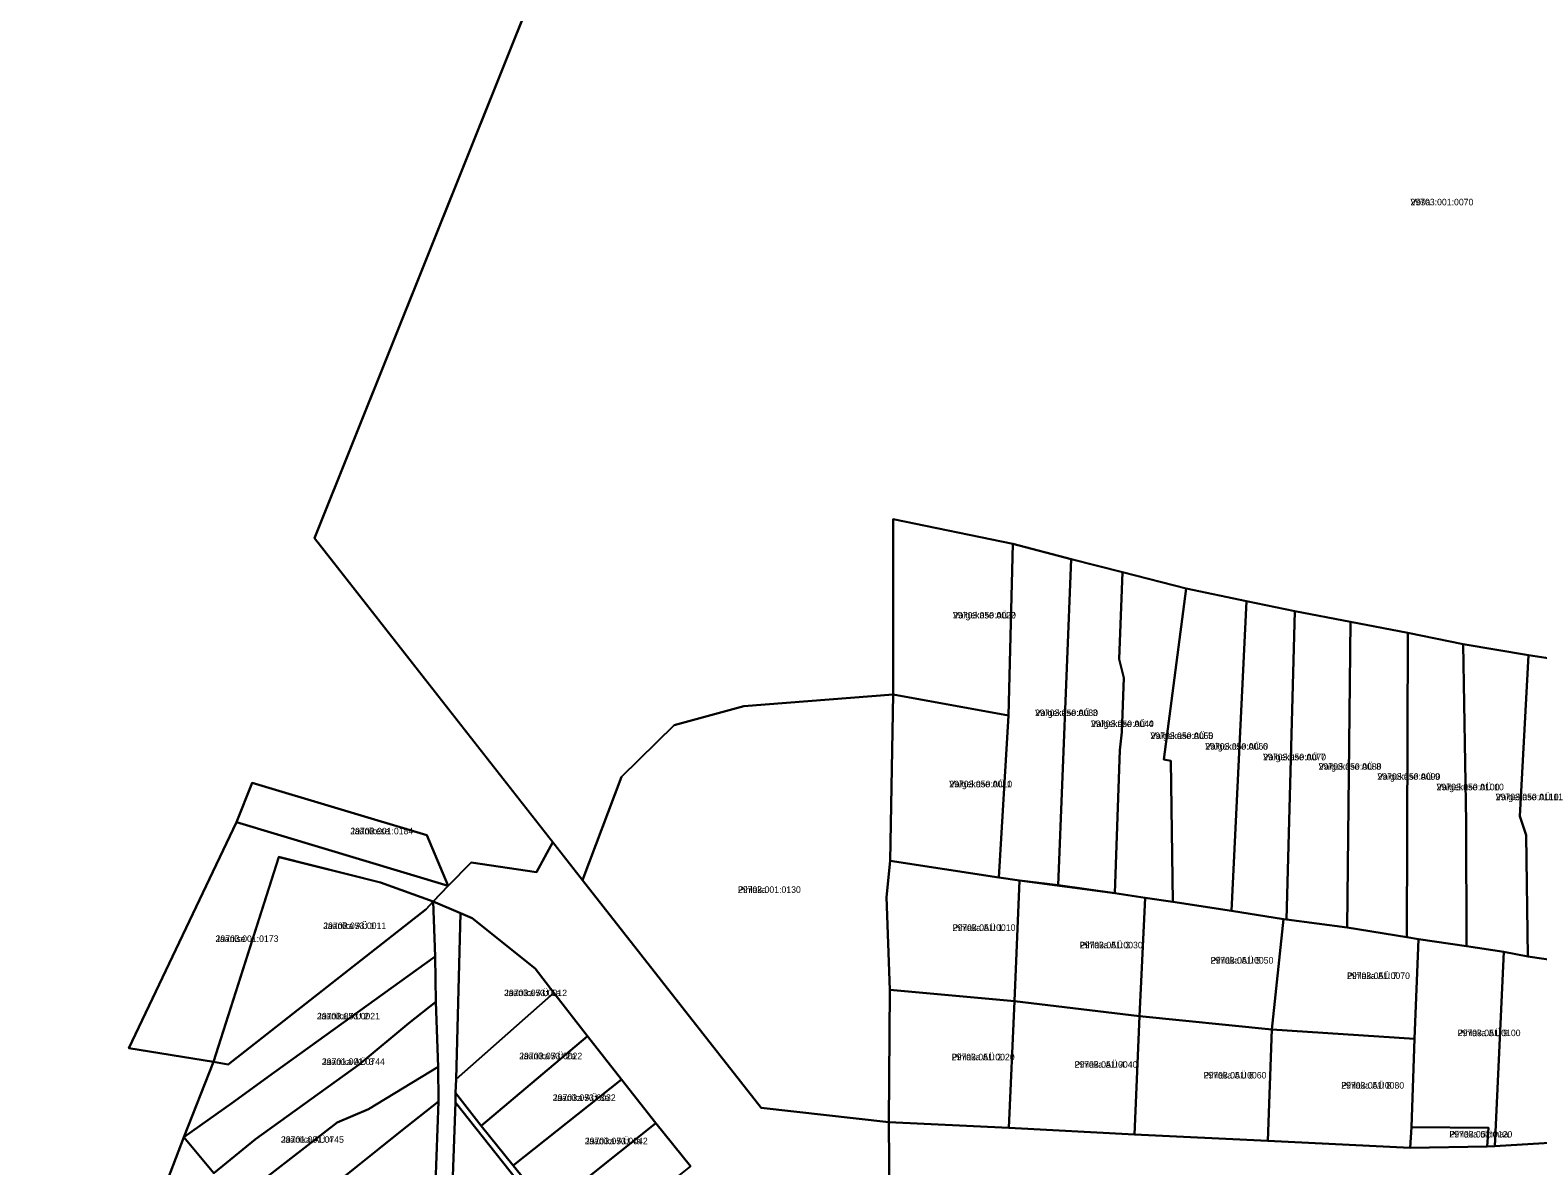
# Model space of a CAD drawing. Extents: x 504287 to 537970, y 6539941 to 6586214.
# Drawn here: x 519918.3 to 520265.8, y 6560574.3 to 6560836.1 of the extents above; entities that cross this region are included whole.
import ezdxf

# ---------------------------------------------------------------- set-up
doc = ezdxf.new("R2010")
doc.units = 0
for name, color, linetype in [('L_AADRESS', 7, 'Continuous'), ('PIIR', 7, 'Continuous'), ('TUNNUS', 7, 'Continuous')]:
    doc.layers.add(name, color=color, linetype=linetype)

msp = doc.modelspace()

# ---------------------------------------------------------------- linework, layer by layer
at = {"layer": 'PIIR'}
for points in [[(520271.61, 6560690.76), (520263.59, 6560691.99), (520248.53, 6560694.54), (520235.8, 6560697.16), (520222.62, 6560699.66), (520209.74, 6560702.15), (520198.62, 6560704.47), (520184.75, 6560707.39), (520170.04, 6560711.12), (520158.24, 6560714.13), (520144.79, 6560717.67), (520117.24, 6560723.36), (520117.22, 6560682.92), (520082.78, 6560680.28), (520066.74, 6560675.85), (520054.61, 6560663.99), (520045.66, 6560640.15), (519983.84, 6560719), (520056.26, 6560899.71)], [(520034.88, 6560846.36), (519983.84, 6560719), (520038.76, 6560648.94), (520035.01, 6560641.99), (520019.98, 6560644.23), (520014.71, 6560638.85), (520009.74, 6560650.5), (519969.54, 6560662.58), (519965.91, 6560653.52), (519941.08, 6560601.39), (519960.59, 6560598.29), (519953.78, 6560580.87), (519946.8, 6560562.5), (519943.46, 6560547.11), (519940.24, 6560531.14), (519938, 6560520.67), (519932.24, 6560494.3), (519926.01, 6560463.67), (519884.76, 6560514.86)], [(520070.55, 6560574.23), (520062.55, 6560584.16), (520054.64, 6560594.18), (520046.76, 6560604.18), (520039.04, 6560614.2), (520034.75, 6560619.78), (520020.24, 6560631.37), (520017.51, 6560632.51), (520011.19, 6560635.24), (520014.71, 6560638.85), (520019.98, 6560644.23), (520035.01, 6560641.99), (520038.76, 6560648.94), (520045.66, 6560640.15), (520086.83, 6560587.63), (520116.2, 6560584.35), (520116.35, 6560565.44)], [(520011.74, 6560570.25), (520012.48, 6560589.11), (520012.38, 6560597.12), (520011.86, 6560612.09), (520011.71, 6560622.51), (520011.19, 6560635.24), (520017.51, 6560632.51), (520016.5, 6560594.3), (520016.36, 6560591.12), (520016.33, 6560588.87), (520014.83, 6560546.37)], [(520036.54, 6560563.34), (520016.33, 6560588.87), (520016.36, 6560591.12), (520022.31, 6560583.51), (520029.67, 6560574.33), (520037.78, 6560564.36)]]:
    msp.add_lwpolyline(points, dxfattribs=at)
for points in [[(520117.24, 6560723.36), (520144.79, 6560717.67), (520143.77, 6560678.14), (520117.22, 6560682.92)], [(520141.59, 6560640.75), (520143.77, 6560678.14), (520144.79, 6560717.67), (520158.24, 6560714.13), (520155.24, 6560638.97), (520146.3, 6560640.09)], [(520158.24, 6560714.13), (520170.04, 6560711.12), (520169.29, 6560691.08), (520170.34, 6560686.77), (520169.91, 6560674.24), (520169.47, 6560670.14), (520168.26, 6560637.17), (520155.24, 6560638.97)], [(520168.26, 6560637.17), (520169.47, 6560670.14), (520169.91, 6560674.24), (520170.34, 6560686.77), (520169.29, 6560691.08), (520170.04, 6560711.12), (520184.75, 6560707.39), (520179.62, 6560667.98), (520181.17, 6560667.66), (520181.69, 6560635.15), (520175.32, 6560636.07)], [(520181.17, 6560667.66), (520179.62, 6560667.98), (520184.75, 6560707.39), (520198.62, 6560704.47), (520195.17, 6560633.08), (520181.69, 6560635.15)], [(520198.62, 6560704.47), (520209.74, 6560702.15), (520207.89, 6560631.08), (520207.16, 6560631.13), (520195.17, 6560633.08)], [(520209.74, 6560702.15), (520222.62, 6560699.66), (520221.81, 6560629.26), (520207.89, 6560631.08)], [(520222.62, 6560699.66), (520235.8, 6560697.16), (520235.55, 6560626.97), (520221.81, 6560629.26)], [(520235.55, 6560626.97), (520235.8, 6560697.16), (520248.53, 6560694.54), (520249.27, 6560653.5), (520249.33, 6560624.96), (520238.26, 6560626.53)], [(520249.27, 6560653.5), (520248.53, 6560694.54), (520263.59, 6560691.99), (520261.64, 6560654.9), (520263.11, 6560650.54), (520263.46, 6560622.57), (520257.91, 6560623.6), (520249.33, 6560624.96)], [(520263.11, 6560650.54), (520261.64, 6560654.9), (520263.59, 6560691.99), (520271.61, 6560690.76), (520272.14, 6560691.85), (520276.25, 6560690.73), (520276.73, 6560687), (520275.62, 6560683.17), (520276.47, 6560664.61), (520277.3, 6560651.87), (520279.05, 6560620.33), (520276.64, 6560620.62), (520263.46, 6560622.57)], [(520116.51, 6560644.62), (520115.69, 6560636.23), (520116.43, 6560614.85), (520116.2, 6560584.35), (520086.83, 6560587.63), (520045.66, 6560640.15), (520054.61, 6560663.99), (520066.74, 6560675.85), (520082.78, 6560680.28), (520117.22, 6560682.92)], [(520117.22, 6560682.92), (520143.77, 6560678.14), (520141.59, 6560640.75), (520116.51, 6560644.62)], [(519969.54, 6560662.58), (520009.74, 6560650.5), (520014.71, 6560638.85), (519965.91, 6560653.52)], [(519965.91, 6560653.52), (520014.71, 6560638.85), (520011.19, 6560635.24), (519999.07, 6560639.62), (519975.64, 6560645.52), (519960.59, 6560598.29), (519941.08, 6560601.39)], [(519999.06, 6560639.6), (520011.19, 6560635.24), (520009.57, 6560633.48), (519964.01, 6560597.62), (519960.62, 6560598.26), (519975.66, 6560645.47)], [(520115.69, 6560636.23), (520116.51, 6560644.62), (520141.59, 6560640.75), (520146.3, 6560640.09), (520145.21, 6560612.28), (520116.43, 6560614.85)], [(520146.3, 6560640.09), (520168.26, 6560637.17), (520175.32, 6560636.07), (520174.01, 6560608.77), (520145.21, 6560612.28)], [(519960.62, 6560598.26), (519964.01, 6560597.62), (520009.57, 6560633.48), (520011.19, 6560635.24), (520011.71, 6560622.51), (519974.69, 6560595.86), (519964.83, 6560588.72), (519953.78, 6560580.87)], [(520175.32, 6560636.07), (520181.69, 6560635.15), (520195.17, 6560633.08), (520207.16, 6560631.13), (520204.49, 6560605.75), (520174.01, 6560608.77)], [(520020.24, 6560631.37), (520034.75, 6560619.78), (520039.04, 6560614.2), (520016.5, 6560594.3), (520017.51, 6560632.51)], [(520207.16, 6560631.13), (520207.89, 6560631.08), (520221.81, 6560629.26), (520235.55, 6560626.97), (520238.26, 6560626.53), (520237.32, 6560603.59), (520204.49, 6560605.75)], [(520237.32, 6560603.59), (520238.26, 6560626.53), (520249.33, 6560624.96), (520257.91, 6560623.6), (520255.84, 6560578.81), (520254.12, 6560578.76), (520254.41, 6560583.04), (520236.68, 6560583.22)], [(519960.65, 6560572.6), (519953.78, 6560580.87), (519964.83, 6560588.72), (519974.69, 6560595.86), (520011.71, 6560622.51), (520011.86, 6560612.09), (520005.63, 6560607.16), (519994.2, 6560597.62), (519970.25, 6560580.41)], [(520257.91, 6560623.6), (520263.46, 6560622.57), (520276.64, 6560620.62), (520274.81, 6560579.95), (520255.84, 6560578.81)], [(519946.8, 6560562.5), (519953.78, 6560580.87), (519960.65, 6560572.6), (519970.25, 6560580.41), (519994.2, 6560597.62), (520005.63, 6560607.16), (520011.86, 6560612.09), (520012.38, 6560597.12), (519996.34, 6560587.33), (519989.12, 6560584.31), (519964.15, 6560564.92), (519966.45, 6560560.06), (519956.05, 6560554.39), (519954.98, 6560556.08), (519943.46, 6560547.11)], [(520016.36, 6560591.12), (520016.5, 6560594.3), (520039.04, 6560614.2), (520046.76, 6560604.18), (520022.31, 6560583.51)], [(520116.43, 6560614.85), (520145.21, 6560612.28), (520143.89, 6560583.03), (520116.2, 6560584.35)], [(520145.21, 6560612.28), (520174.01, 6560608.77), (520172.86, 6560581.52), (520143.89, 6560583.03)], [(520174.01, 6560608.77), (520204.49, 6560605.75), (520203.54, 6560580.07), (520172.86, 6560581.52)], [(520204.49, 6560605.75), (520237.32, 6560603.59), (520236.68, 6560583.22), (520236.32, 6560578.42), (520203.54, 6560580.07)], [(520022.31, 6560583.51), (520046.76, 6560604.18), (520054.64, 6560594.18), (520029.67, 6560574.33)], [(519940.24, 6560531.14), (519943.46, 6560547.11), (519954.98, 6560556.08), (519956.05, 6560554.39), (519966.45, 6560560.06), (519964.15, 6560564.92), (519989.12, 6560584.31), (519996.34, 6560587.33), (520012.38, 6560597.12), (520012.48, 6560589.11), (520003.68, 6560582.19), (519998.59, 6560578.1), (519993.62, 6560574.1), (519966.07, 6560551.93)], [(520029.67, 6560574.33), (520054.64, 6560594.18), (520062.55, 6560584.16), (520037.78, 6560564.36)], [(519966.08, 6560551.94), (519993.62, 6560574.1), (519998.59, 6560578.1), (520003.68, 6560582.19), (520012.48, 6560589.11), (520011.74, 6560570.25), (519972.17, 6560543.68)], [(520036.54, 6560563.34), (520014.83, 6560546.37), (520016.33, 6560588.87)], [(520037.78, 6560564.36), (520062.55, 6560584.16), (520070.55, 6560574.23), (520045.75, 6560554.35)], [(520116.2, 6560584.35), (520143.89, 6560583.03), (520172.86, 6560581.52), (520203.54, 6560580.07), (520236.32, 6560578.42), (520254.12, 6560578.76), (520255.84, 6560578.81), (520274.81, 6560579.95), (520296.22, 6560581), (520324.82, 6560582.86), (520329.36, 6560563.63), (520310.39, 6560562.71), (520295.35, 6560561.83), (520280.17, 6560560.87), (520265.21, 6560560.11), (520249.8, 6560559.14), (520244.74, 6560558.9), (520234.71, 6560559.27), (520219.94, 6560560.24), (520173.38, 6560562.51), (520162.65, 6560563.03), (520116.35, 6560565.44)], [(520236.68, 6560583.22), (520254.41, 6560583.04), (520254.12, 6560578.76), (520236.32, 6560578.42)]]:
    msp.add_lwpolyline(points, close=True, dxfattribs=at)

# ---------------------------------------------------------------- texts
at = {"layer": 'L_AADRESS'}
for s, p in [('Võsa', (520236.42, 6560795.72)), ('Valgekase AÜ 2', (520131, 6560700.48)), ('Valgekase AÜ 3', (520149.92, 6560677.98)), ('Valgekase AÜ 4', (520162.79, 6560675.45)), ('Valgekase AÜ 5', (520176.5, 6560672.69)), ('Valgekase AÜ 6', (520189.12, 6560670.24)), ('Valgekase AÜ 7', (520202.46, 6560667.78)), ('Valgekase AÜ 8', (520215.25, 6560665.6)), ('Valgekase AÜ 9', (520228.8, 6560663.29)), ('Valgekase AÜ 1', (520130.14, 6560661.56)), ('Valgekase AÜ 10', (520242.44, 6560660.87)), ('Valgekase AÜ 11', (520256.06, 6560658.58)), ('Jaanikese', (519992.13, 6560650.71)), ('Pihlaka', (520081.44, 6560637.21)), ('Jaanika AÜ 1', (519985.9, 6560628.88)), ('Pihlaka AÜ 1', (520130.9, 6560628.45)), ('Jaanise', (519961.07, 6560625.9)), ('Pihlaka AÜ 3', (520160.22, 6560624.43)), ('Pihlaka AÜ 5', (520190.34, 6560620.91)), ('Pihlaka AÜ 7', (520221.8, 6560617.36)), ('Jaanika AÜ 1a', (520027.57, 6560613.41)), ('Jaanika AÜ 2', (519984.45, 6560608.05)), ('Pihlaka AÜ 9', (520247.29, 6560604.18)), ('Jaanika AÜ 3', (519985.58, 6560597.56)), ('Jaanika AÜ 2a', (520031.06, 6560598.86)), ('Pihlaka AÜ 2', (520130.71, 6560598.62)), ('Pihlaka AÜ 4', (520159.01, 6560596.9)), ('Pihlaka AÜ 6', (520188.74, 6560594.42)), ('Jaanika AÜ 3a', (520038.78, 6560589.25)), ('Pihlaka AÜ 8', (520220.47, 6560592.09)), ('Jaanika AÜ 4', (519976.15, 6560579.6)), ('Jaanika AÜ 4a', (520046.16, 6560579.27)), ('Pihlaka üldmaa', (520245.38, 6560580.82))]:
    msp.add_text(s, height=1.5, dxfattribs=at).set_placement(p)
at = {"layer": 'TUNNUS'}
for s, p in [('29703:001:0070', (520236.42, 6560795.72)), ('29703:050:0020', (520131, 6560700.48)), ('29703:050:0030', (520149.92, 6560677.98)), ('29703:050:0040', (520162.79, 6560675.45)), ('29703:050:0050', (520176.5, 6560672.69)), ('29703:050:0060', (520189.12, 6560670.24)), ('29703:050:0070', (520202.46, 6560667.78)), ('29703:050:0080', (520215.25, 6560665.6)), ('29703:050:0090', (520228.8, 6560663.29)), ('29703:050:0010', (520130.14, 6560661.56)), ('29703:050:0100', (520242.44, 6560660.87)), ('29703:050:0110', (520256.06, 6560658.58)), ('29703:001:0184', (519992.13, 6560650.71)), ('29703:001:0130', (520081.44, 6560637.21)), ('29703:053:0011', (519985.9, 6560628.88)), ('29703:051:0010', (520130.9, 6560628.45)), ('29703:001:0173', (519961.07, 6560625.9)), ('29703:051:0030', (520160.22, 6560624.43)), ('29703:051:0050', (520190.34, 6560620.91)), ('29703:051:0070', (520221.8, 6560617.36)), ('29703:053:0012', (520027.57, 6560613.41)), ('29703:053:0021', (519984.45, 6560608.05)), ('29703:051:0100', (520247.29, 6560604.18)), ('29701:001:0744', (519985.58, 6560597.56)), ('29703:053:0022', (520031.06, 6560598.86)), ('29703:051:0020', (520130.71, 6560598.62)), ('29703:051:0040', (520159.01, 6560596.9)), ('29703:051:0060', (520188.74, 6560594.42)), ('29703:051:0080', (520220.47, 6560592.09)), ('29703:053:0032', (520038.78, 6560589.25)), ('29701:001:0745', (519976.15, 6560579.6)), ('29703:053:0042', (520046.16, 6560579.27)), ('29703:051:0120', (520245.38, 6560580.82))]:
    msp.add_text(s, height=1.5, dxfattribs=at).set_placement(p)

doc.saveas('drawing.dxf')
